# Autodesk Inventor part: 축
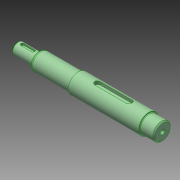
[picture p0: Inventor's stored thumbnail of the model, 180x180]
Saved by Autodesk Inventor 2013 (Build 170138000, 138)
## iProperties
Created: 2024-01
Part Number: 축
Material: 강철, 탄소
Document SubType Name: Modeling
Designer: mdu-01
Density: 1 g/cm^3
Author: mdu-01
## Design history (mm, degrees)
sketch "스케치1"
  geometry: L1 (0, 0)-(118.751, 0); L2 (124, 2.125)-(124, 6.5); L3 (123, 7.5)-(112.6, 7.5); L4 (112, 8.1)-(112, 8.5); L5 (112, 8.5)-(52, 8.5); L6 (52, 8.5)-(52, 8.1); L7 (51.4, 7.5)-(20.268, 7.5); L8 (18, 5.923)-(18, 5); L9 (18, 5)-(1, 5); L10 (0, 4)-(0, 0); L11 (124, 2.125)-(122.051, 1); L12 (122.051, 1)-(119.329, 1); L13 (119.329, 1)-(118.751, 0); L14 (124, 6.5)-(123, 7.5); L15 (1, 5)-(0, 4); L16 (18.5, 6.789)-(19.268, 7.232); A1 r 0.6 centre (51.4, 8.1) between (51.4, 7.5) and (52, 8.1); A2 r 0.6 centre (112.6, 8.1) between (112, 8.1) and (112.6, 7.5); A3 r 2 centre (20.268, 5.5) between (20.268, 7.5) and (19.268, 7.232); A4 r 1 centre (19, 5.923) between (18.5, 6.789) and (18, 5.923); 3 further points
  constraints: 32 end point, 8 parallel, 8 point on circle, 8 tangent, 6 point on line, 4 centre point, 2 horizontal, 1 collinear, 1 equal radius, 1 perpendicular
  dimensions: "d0" = 2 diameter of L12 L1; "d2" = 4.25 diameter of L2.start L1; "d3" = 30 deg angle of L1 L11; "d4" = 60 deg angle of L1 L13; "d5" = 3.3 horizontal distance of L1.end L11.end; "d6" = 124 distance between parallel lines of L10 L2; "d7" = 12 distance between parallel lines of L4 L2; "d8" = 34 distance between parallel lines of L6 L8; "d9" = 18 distance between parallel lines of L8 L10; "d10" = 10 diameter of L9 L1; "d11" = 15 diameter of L7 L1; "d12" = 17 diameter of L5 L1; "d13" = 0.6 radius of A1; "d14" = 1 distance of L2.end point (124, 7.5); "d15" = 1 distance of L3.start point (124, 7.5) (= d14); "d16" = 1 distance of L9.end point (0, 5) (= d14); "d17" = 1 distance of L10.start point (0, 5) (= d16); "d18" = 13 diameter of point (18, 6.5) L1; "d19" = 30 deg angle of L7 L16; "d20" = 2 radius of A3; "d21" = 1 radius of A4
revolve "회전1" sketch "스케치1" stored, may be unused: angle "d22" = 90 deg
hole "구멍1" diameter "d25" = 3.242; stored, may be unused: countersink angle "d29" = 90 deg, drill point angle "d31" = 118 deg; dims "d23" = 10, "d24" = 10, "d26" = 8, "d27" = 4, "d28" = 2, "d30" = 10
sketch "스케치2"
  geometry: L1 (0, -1.621)-(0, 1.621) reference; L2 (0, -4)-(0, 4) reference; L3 (0, 0)-(4.59, 0); L4 (4.59, 0)-(0, 2.65); L5 (0, 2.65)-(0, 0)
  constraints: 6 end point, 1 collinear, 1 perpendicular, 1 point on line
  dimensions: "d32" = 30 deg angle of L3 L4; "d33" = 5.3 diameter of L4.end L3
revolve "회전2" sketch "스케치2" stored, may be unused: angle "d35" = 90 deg
sketch "스케치3"
  geometry: L1 (18, -5)-(18, 5) reference; L2 (1, -5)-(1, 5) reference; L3 (3, 5)-(15, 5); L4 (15, 5)-(15, 3.2); L5 (15, 3.2)-(3, 3.2); L6 (3, 3.2)-(3, 5); 1 further point
  constraints: 8 end point, 2 parallel, 1 horizontal, 1 perpendicular, 1 point on line
  dimensions: "d36" = 3 distance between parallel lines of L4 L1; "d37" = 12 distance between parallel lines of L6 L4; "d38" = 1.8 distance between parallel lines of L5 L3
extrude "돌출1" cut sketch "스케치3" stored distance "d39" = 3; taper "d40" = 0 deg
fillet "모깎기1"
fillet "모깎기2"
sketch "스케치4"
  geometry: L1 (112, -8.5)-(112, 8.5) reference; L2 (52, -8.5)-(52, 8.5) reference; L3 (66, 8.5)-(98, 8.5); L4 (98, 8.5)-(98, 5.5); L5 (98, 5.5)-(66, 5.5); L6 (66, 5.5)-(66, 8.5); 1 further point
  constraints: 8 end point, 2 parallel, 1 horizontal, 1 perpendicular, 1 point on line
  dimensions: "d41" = 14 distance between parallel lines of L6 L2; "d42" = 32 distance between parallel lines of L4 L6; "d43" = 3 distance between parallel lines of L5 L3
extrude "돌출2" cut sketch "스케치4" stored distance "d44" = 5; taper "d45" = 0 deg
fillet "모깎기3"
fillet "모깎기4"
node "솔리드1"
node "투영된 루프1"
node "투영된 루프2"
node "투영된 루프3"
